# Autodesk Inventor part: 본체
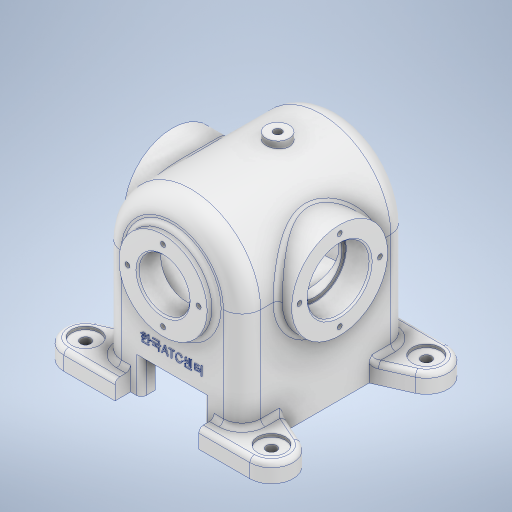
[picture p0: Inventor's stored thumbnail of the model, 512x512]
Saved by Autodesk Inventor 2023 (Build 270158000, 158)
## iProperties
Created: 2024-09
Part Number: 본체
Material: 알루미늄 6061
Document SubType Name: Modeling
Designer: home
Mass: 1791.16 g
Surface Area: 1101 cm^2
Volume: 663.393 cm^3
Density: 2.7 g/cm^3
Appearance: 알루미늄 - 평지
Author: home
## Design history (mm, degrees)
sketch "스케치1"
  geometry: L1 (-45, 76)-(-45, 0); L2 (45, 76)-(45, 0); L3 (-20, 23)-(-20, 0); L4 (-20, 23)-(20, 23); L5 (20, 23)-(20, 0); L6 (-45, 0)-(-20, 0); L7 (20, 0)-(45, 0); A1 r 45 centre (0, 76) between (45, 76) and (-45, 76); 2 further points
  constraints: 14 end point, 4 vertical, 3 horizontal, 2 point on circle, 2 tangent, 2 vertical alignment, 1 centre point, 1 midpoint
  dimensions: "d0" = 90 diameter of A1; "d1" = 76 distance of point (0, 0) A1.centre; "d2" = 40 distance of L5.end L3.end; "d3" = 20 distance of L3.end point (0, 0); "d4" = 23 distance of L4.end L5.end; "d5" = 25 distance between parallel lines of L2 L5
extrude "돌출1" new body sketch "스케치1" stored distance "d6" = 108; taper "d7" = 0 deg
sketch "스케치2"
  geometry: C1 r 28.5 at (0, 76); A1 r 45 centre (0, 76) between (45, 76) and (-45, 76) reference; 1 further point
  constraints: 1 centre point, 1 coincident
  dimensions: "d8" = 57 diameter of C1
extrude "돌출2" join sketch "스케치2" distance "d9" = 6; taper "d10" = 0 deg
sketch "스케치3"
  geometry: C1 r 28.5 at (0, 0) reference; C2 r 16.5 at (0, 0); 1 further point
  constraints: 1 centre point, 1 coincident
  dimensions: "d11" = 33 diameter of C2
extrude "돌출3" cut sketch "스케치3" distance "d12" = 105; taper "d13" = 0 deg
sketch "스케치4"
  geometry: C1 r 28.5 at (0, 0) reference; 5 further points
  constraints: 1 vertical alignment, 5 other
  dimensions: "d14" = 23 distance of C1.centre point (0, 23); "d17" = 360 deg dimension on C1.centre point (0, 23) (derived)
hole "구멍1" sketch "스케치4" at (0, 23), (-23, 0), (0, -23), (23, 0) diameter "d19" = 3.242; stored, may be unused: countersink angle "d23" = 90 deg, drill point angle "d25" = 118 deg; dims "d20" = 8, "d21" = 4, "d22" = 2, "d24" = 10
node "작업 평면1"
sketch "스케치5"
  geometry: C1 r 31 at (76, 0); 1 further point
  constraints: 1 centre point, 1 horizontal alignment
  dimensions: "d27" = 62 diameter of C1; "d28" = 76 distance of point (0, 0) C1.centre
extrude "돌출4" join sketch "스케치5" stored distance "d29" = 105; taper "d30" = 0 deg
sketch "스케치6"
  geometry: C1 r 31 at (0, 0) reference; 5 further points
  constraints: 1 vertical alignment, 5 other
  dimensions: "d31" = 26 distance of C1.centre point (0, 26); "d34" = 360 deg dimension on C1.centre point (0, 26) (derived)
hole "구멍2" sketch "스케치6" at (0, 26), (-26, 0), (0, -26), (26, 0) diameter "d36" = 3.242; stored, may be unused: countersink angle "d40" = 90 deg, drill point angle "d42" = 118 deg; dims "d37" = 8, "d38" = 4, "d39" = 2, "d41" = 10
sketch "스케치7"
  geometry: C1 r 31 at (0, 0) reference; C2 r 20 at (0, 0); 1 further point
  constraints: 1 centre point, 1 coincident
  dimensions: "d43" = 40 diameter of C2
extrude "돌출5" cut sketch "스케치7" distance "d44" = 16; taper "d45" = 0 deg
sketch "스케치8"
  geometry: C1 r 20 at (0, 0) reference; C2 r 17.5 at (0, 0); 1 further point
  constraints: 1 centre point, 1 coincident
  dimensions: "d46" = 35 diameter of C2
sketch "스케치9"
  geometry: L1 (60, -64)-(27, -64); L2 (65.693, -37.21)-(45, -28); L3 (45, -54)-(45, 54) reference; L4 (27, -64)-(27, -54); L5 (-45, -54)-(45, -54) reference; L6 (-60, -64)-(-27, -64); L7 (-27, -64)-(-27, -54); L8 (-45, -54)-(-45, 54) reference; L9 (-65.693, -37.21)-(-45, -28); L10 (45, -28)-(45, -54); L11 (45, -54)-(27, -54); L12 (-45, -28)-(-45, -54); L13 (-45, -54)-(-27, -54); A1 r 14 centre (60, -50) between (60, -64) and (65.693, -37.21); A2 r 14 centre (-60, -50) between (-65.729, -37.226) and (-60, -64); 2 further points
  constraints: 20 end point, 5 point on circle, 4 collinear, 4 point on line, 3 tangent, 2 centre point, 2 horizontal, 1 equal radius, 1 midpoint, 1 perpendicular, 1 vertical
  dimensions: "d47" = 120 distance of A2.centre A1.centre; "d48" = 60 horizontal distance of point (0, 0) A1.centre; "d49" = 50 vertical distance of point (0, 0) A1.centre; "d50" = 28 diameter of A1; "d51" = 36 vertical distance of L2.end L1.start; "d52" = 18 distance from line of L1.end L3; "d53" = 64 vertical distance of point (0, 0) L1.start; "d54" = 50 vertical distance of point (0, 0) A2.centre; "d55" = 18 distance from line of point (-27, -59) L8; "d57" = 36 vertical distance of L6.start L9.end
extrude "돌출6" join sketch "스케치9" distance "d58" = 12; taper "d59" = 0 deg
extrude "돌출8" cut sketch "스케치8" extent not by distance; stored distance "d66" = 40; taper "d67" = 0 deg
node "작업 평면2"
sketch "스케치12"
  geometry: C1 r 36 at (0, 76); A1 r 45 centre (0, 76) between (45, 76) and (-45, 76) reference; 1 further point
  constraints: 1 centre point, 1 coincident
  dimensions: "d69" = 9 radial gap between concentric circles of C1 A1
extrude "돌출9" cut sketch "스케치12" distance "d70" = 90; taper "d71" = 0 deg
node "작업 평면3"
chamfer "모따기1" distance "d93" = 1; stored, may be unused: second distance "d94" = 2, angle "d95" = 45 deg
fillet "모깎기1" dims "d96" = 0.3
sketch "스케치17"
  geometry: L1 (28.5, 60)-(-28.5, 60) reference; C1 r 7.5 at (0, -14); 1 further point
  constraints: 1 centre point, 1 vertical alignment
  dimensions: "d97" = 15 diameter of C1; "d98" = 74 distance from line of L1 C1.centre
extrude "돌출12" join sketch "스케치17" stored distance "d99" = 4; taper "d100" = 0 deg; dims "d5" = 25
sketch "스케치18"
  geometry: C1 r 7.5 at (0, 0) reference; 2 further points
  constraints: 1 coincident
hole "구멍5" sketch "스케치18" at (0, 0) diameter "d101" = 5.1881; stored, may be unused: countersink angle "d105" = 90 deg, drill point angle "d107" = 0 deg; dims "d102" = 12, "d103" = 4, "d104" = 2, "d106" = 8
fillet "모깎기2" dims "d120" = 12
sketch "스케치21"
  geometry: A1 r 14 centre (33, 14) between (33, 0) and (38.693, 26.79) reference; A2 r 14 centre (-87, 14) between (-92.693, 26.79) and (-87, 0) reference; 3 further points
  constraints: 2 coincident
hole "구멍7" sketch "스케치21" at (-87, 14), (33, 14) diameter "d121" = 6.6; stored, may be unused: countersink angle "d125" = 90 deg, drill point angle "d127" = 0 deg; dims "d122" = 12, "d123" = 18, "d124" = 2, "d126" = 8
fillet "모깎기3" dims "d128" = 3
sketch "스케치22"
  geometry: L1 (27, 0)-(60, 0) reference; 2 further points
  constraints: 1 vertical alignment, 1 other
  dimensions: "d129" = 35 distance from line of L1 point (0, 35)
feature "엠보싱1" sketch "스케치22" dims "d0" = 90, "d1" = 76, "d2" = 40, "d3" = 20, "d4" = 23, "d5" = 25, "d8" = 57, "d130" = 0.5, "d131" = 0
fillet "모깎기4" dims "d132" = 3
fillet "모깎기5" dims "d133" = 3
sketch "스케치23"
  geometry: L1 (18, 106)-(-72, 106) reference; L2 (9, 19)-(-7, 19); L3 (-7, 19)-(-7, 109); L4 (-7, 109)-(9, 109); L5 (9, 109)-(9, 19); L6 (18, 36)-(18, 92) reference; L7 (-4, 10)-(-50, 10) reference; L8 (-4, 118)-(0, 118) reference; L9 (-7, 13)-(-7, 115) reference; 2 further points
  constraints: 8 end point, 2 parallel, 1 horizontal, 1 perpendicular, 1 vertical alignment
  dimensions: "d137" = 9 distance between parallel lines of L6 L5; "d138" = 9 distance between parallel lines of L7 L2; "d139" = 9 distance between parallel lines of L8 L4
extrude "돌출15" cut sketch "스케치23" stored distance "d142" = 10; taper "d143" = 0 deg
node "솔리드1"
mirror "미러1"
mirror "미러2"
mirror "미러4"
mirror "미러5"
mirror "미러7"
feature "A9D066F2-1C7D-4E18-AEED-F7BC21143FA4" dims "d121" = 6.6, "d122" = 12, "d123" = 18, "d124" = 2, "d125" = 90 deg, "d126" = 8, "d127" = 0
other parameters: "d26" = 54, "d68" = -9, "d72" = 125
